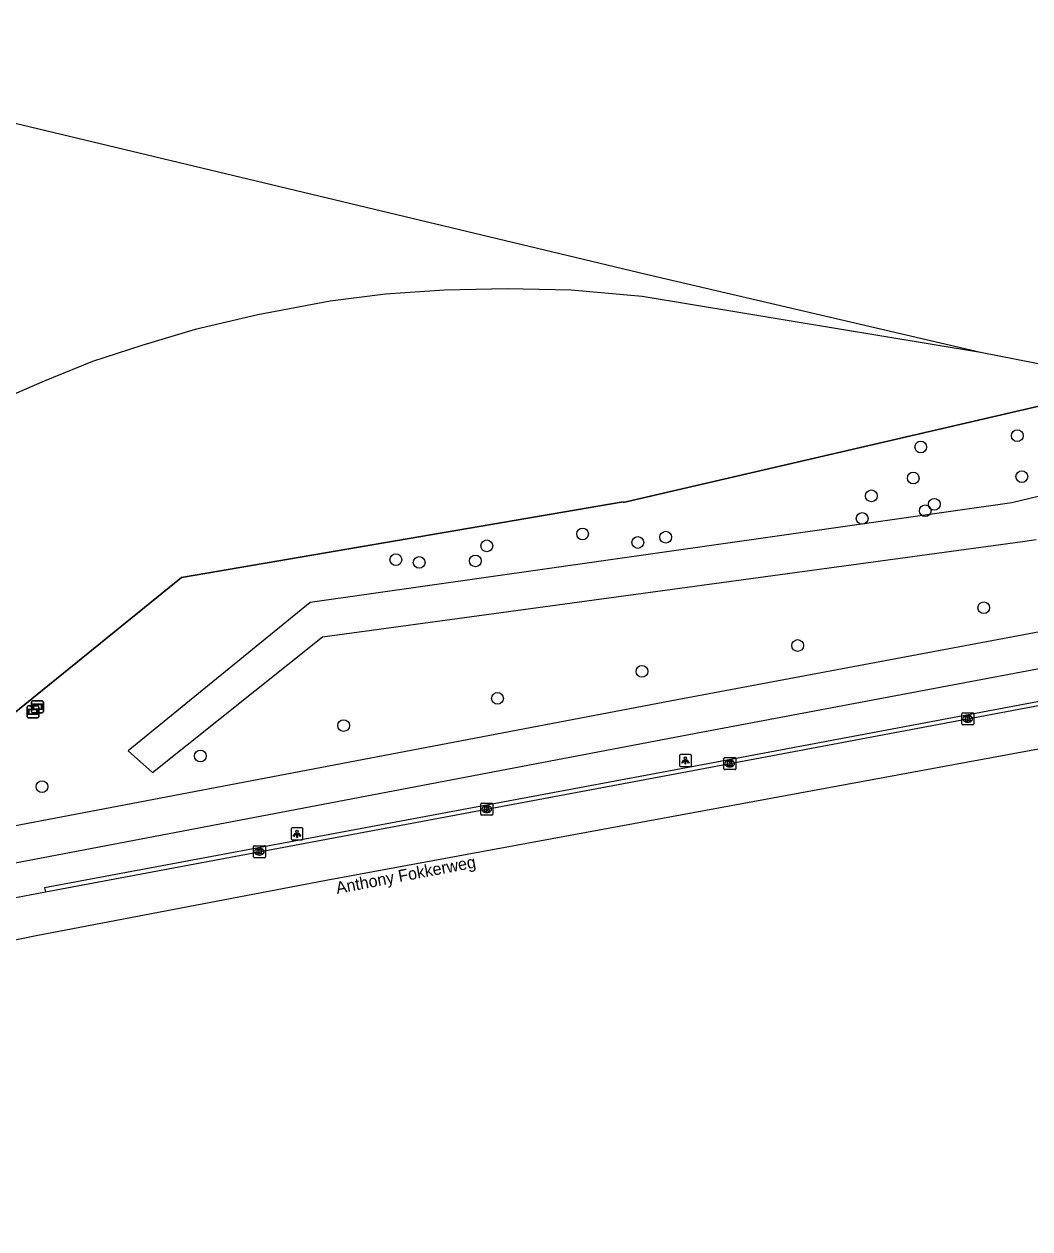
# Model space of a CAD drawing. Extents: x 156141 to 158132, y 385651 to 388399.
# Drawn here: x 157692.2 to 157776, y 386390.2 to 386490.4 of the extents above; entities that cross this region are included whole.
import ezdxf

# ---------------------------------------------------------------- set-up
doc = ezdxf.new("R2010")
doc.units = 0
for name, color, linetype in [('IMGEO_Boom', 7, 'Continuous'), ('IMGEO_Fietspad_gesloten', 7, 'Continuous'), ('IMGEO_Groenvoorziening', 7, 'Continuous'), ('IMGEO_Hek', 7, 'Continuous'), ('IMGEO_Kolk', 7, 'Continuous'), ('IMGEO_Lichtpunt', 7, 'Continuous'), ('IMGEO_Openbare_ruimte_label', 7, 'Continuous'), ('IMGEO_Rijbaan_regionaal_gesloten', 7, 'Continuous'), ('IMGEO_Spoor', 7, 'Continuous'), ('IMGEO_Verkeerseiland_open', 7, 'Continuous'), ('IMGEO_Verklikker', 7, 'Continuous')]:
    doc.layers.add(name, color=color, linetype=linetype)

msp = doc.modelspace()

# ---------------------------------------------------------------- linework, layer by layer
at = {"layer": 'IMGEO_Boom'}
for centre in [(157774.9, 386456.2), (157766.87, 386455.26), (157775.28, 386452.8), (157766.24, 386452.68), (157762.76, 386451.2), (157767.24, 386449.96), (157768, 386450.5), (157761.99, 386449.32), (157738.72, 386448.03), (157745.64, 386447.76), (157730.75, 386447.04), (157743.32, 386447.32), (157723.18, 386445.89), (157729.8, 386445.79), (157725.12, 386445.66), (157772.11, 386441.89), (157756.62, 386438.75), (157743.66, 386436.6), (157731.64, 386434.35), (157718.83, 386432.09), (157706.91, 386429.56), (157693.73, 386427.01)]:
    msp.add_circle(centre, 0.489, dxfattribs=at)
at = {"layer": 'IMGEO_Fietspad_gesloten'}
for points in [[(157813.76, 386446.82), (157746.6, 386434.23), (157685.54, 386422.6), (157681.31, 386421.73), (157676.8, 386420.73)], [(157677.29, 386417.7), (157686.09, 386419.66), (157747.11, 386431.27), (157814.29, 386443.91)]]:
    msp.add_lwpolyline(points, dxfattribs=at)
at = {"layer": 'IMGEO_Groenvoorziening'}
for points in [[(157679.82, 386423.74), (157705.33, 386444.41), (157742.09, 386450.7), (157742.11, 386450.66), (157779.34, 386459.26)], [(157799.75, 386456.7), (157774.45, 386450.61), (157716.05, 386442.34), (157700.91, 386430), (157702.93, 386428.18), (157717.07, 386439.48), (157775.34, 386447.41), (157776.46, 386447.56)]]:
    msp.add_lwpolyline(points, dxfattribs=at)
at = {"layer": 'IMGEO_Hek'}
for points in [[(157779.34, 386459.26), (157742.11, 386450.66), (157742.09, 386450.7), (157705.33, 386444.41)], [(157705.33, 386444.41), (157679.82, 386423.74)]]:
    msp.add_lwpolyline(points, dxfattribs=at)
at = {"layer": 'IMGEO_Kolk'}
for p, q in [((157770.36, 386433.16), (157771.21, 386433.16)), ((157770.28, 386432.23), (157770.28, 386433.08)), ((157771.21, 386432.15), (157770.36, 386432.15)), ((157770.77, 386432.93), (157770.79, 386432.93)), ((157770.79, 386432.38), (157770.77, 386432.38)), ((157771.28, 386433.08), (157771.28, 386432.23)), ((157750.47, 386428.5), (157750.47, 386429.35)), ((157750.55, 386429.43), (157751.4, 386429.43)), ((157750.96, 386429.21), (157750.99, 386429.21)), ((157751.47, 386429.35), (157751.47, 386428.5)), ((157751.4, 386428.43), (157750.55, 386428.43)), ((157750.98, 386428.65), (157750.96, 386428.65)), ((157730.25, 386424.71), (157730.25, 386425.56)), ((157730.32, 386425.64), (157731.17, 386425.64)), ((157730.73, 386425.42), (157730.76, 386425.42)), ((157731.25, 386425.56), (157731.25, 386424.71)), ((157731.17, 386424.64), (157730.32, 386424.64)), ((157730.76, 386424.86), (157730.73, 386424.86)), ((157711.32, 386421.17), (157711.32, 386422.03)), ((157711.39, 386422.1), (157712.25, 386422.1)), ((157711.83, 386421.32), (157711.8, 386421.32)), ((157711.81, 386421.88), (157711.83, 386421.88)), ((157712.32, 386422.03), (157712.32, 386421.17)), ((157712.25, 386421.1), (157711.39, 386421.1))]:
    msp.add_line(p, q, dxfattribs=at)
for points in [[(157770.36, 386433.16), (157771.21, 386433.16)], [(157770.28, 386432.23), (157770.28, 386433.08)], [(157771.21, 386432.15), (157770.36, 386432.15)], [(157770.6, 386432.85), (157770.73, 386432.85), (157770.73, 386432.7), (157770.85, 386432.85), (157771.02, 386432.85), (157770.87, 386432.7), (157771.03, 386432.45), (157770.87, 386432.45), (157770.79, 386432.62), (157770.73, 386432.55), (157770.73, 386432.45), (157770.6, 386432.45), (157770.6, 386432.85)], [(157771.28, 386433.08), (157771.28, 386432.23)], [(157750.47, 386428.5), (157750.47, 386429.35)], [(157750.55, 386429.43), (157751.4, 386429.43)], [(157750.79, 386429.13), (157750.92, 386429.13), (157750.92, 386428.98), (157751.05, 386429.13), (157751.21, 386429.13), (157751.06, 386428.98), (157751.22, 386428.73), (157751.06, 386428.73), (157750.98, 386428.89), (157750.92, 386428.83), (157750.92, 386428.73), (157750.79, 386428.73), (157750.79, 386429.13)], [(157751.47, 386429.35), (157751.47, 386428.5)], [(157751.4, 386428.43), (157750.55, 386428.43)], [(157730.25, 386424.71), (157730.25, 386425.56)], [(157730.32, 386425.64), (157731.17, 386425.64)], [(157730.57, 386425.34), (157730.69, 386425.34), (157730.69, 386425.19), (157730.82, 386425.34), (157730.98, 386425.34), (157730.84, 386425.19), (157730.99, 386424.94), (157730.84, 386424.94), (157730.75, 386425.1), (157730.69, 386425.03), (157730.69, 386424.94), (157730.57, 386424.94), (157730.57, 386425.34)], [(157731.25, 386425.56), (157731.25, 386424.71)], [(157731.17, 386424.64), (157730.32, 386424.64)], [(157711.32, 386421.17), (157711.32, 386422.03)], [(157711.39, 386422.1), (157712.25, 386422.1)], [(157711.64, 386421.8), (157711.76, 386421.8), (157711.76, 386421.65), (157711.89, 386421.8), (157712.06, 386421.8), (157711.91, 386421.65), (157712.06, 386421.4), (157711.91, 386421.4), (157711.83, 386421.56), (157711.76, 386421.5), (157711.76, 386421.4), (157711.64, 386421.4), (157711.64, 386421.8)], [(157712.32, 386422.03), (157712.32, 386421.17)], [(157712.25, 386421.1), (157711.39, 386421.1)]]:
    msp.add_lwpolyline(points, dxfattribs=at)
for centre, start, end in [((157770.36, 386433.08), 91.552, 178.448), ((157770.36, 386433.08), 91.552, 178.448), ((157771.21, 386433.08), 1.552, 88.448), ((157771.21, 386433.08), 1.552, 88.448), ((157770.36, 386432.23), 181.552, 268.448), ((157770.36, 386432.23), 181.552, 268.448), ((157771.21, 386432.23), 271.552, 358.448), ((157771.21, 386432.23), 271.552, 358.448), ((157750.55, 386429.35), 91.552, 178.448), ((157750.55, 386429.35), 91.552, 178.448), ((157751.4, 386429.35), 1.552, 88.448), ((157751.4, 386429.35), 1.552, 88.448), ((157750.55, 386428.5), 181.552, 268.448), ((157750.55, 386428.5), 181.552, 268.448), ((157751.4, 386428.5), 271.552, 358.448), ((157751.4, 386428.5), 271.552, 358.448), ((157730.32, 386425.56), 91.552, 178.448), ((157730.32, 386425.56), 91.552, 178.448), ((157731.17, 386425.56), 1.552, 88.448), ((157731.17, 386425.56), 1.552, 88.448), ((157730.32, 386424.71), 181.552, 268.448), ((157730.32, 386424.71), 181.552, 268.448), ((157731.17, 386424.71), 271.552, 358.448), ((157731.17, 386424.71), 271.552, 358.448), ((157711.4, 386422.02), 91.552, 178.448), ((157711.4, 386422.02), 91.552, 178.448), ((157711.4, 386421.17), 181.552, 268.448), ((157711.4, 386421.17), 181.552, 268.448), ((157712.24, 386422.02), 1.552, 88.448), ((157712.24, 386422.02), 1.552, 88.448), ((157712.24, 386421.17), 271.552, 358.448), ((157712.24, 386421.17), 271.552, 358.448)]:
    msp.add_arc(centre, 0.0765, start, end, dxfattribs=at)
for centre, major_axis, ratio, start_param, end_param in [((157770.77, 386432.65), (-0.387, 0.002), 0.722429, 4.712389, 7.853982), ((157770.79, 386432.65), (-0.39, 0.002), 0.717154, 1.570796, 4.712389), ((157750.96, 386428.93), (-0.387, 0.002), 0.722429, 4.712389, 7.853982), ((157750.98, 386428.93), (-0.39, 0.002), 0.717154, 1.570796, 4.712389), ((157730.73, 386425.14), (-0.387, 0.002), 0.722429, 4.712389, 7.853982), ((157730.76, 386425.14), (-0.39, 0.002), 0.717154, 1.570796, 4.712389), ((157711.81, 386421.6), (-0.387, 0.002), 0.722429, 4.712389, 7.853982), ((157711.83, 386421.6), (-0.39, 0.002), 0.717154, 1.570796, 4.712389)]:
    msp.add_ellipse(centre, major_axis=major_axis, ratio=ratio, start_param=start_param, end_param=end_param, dxfattribs=at)
at = {"layer": 'IMGEO_Lichtpunt'}
for p, q in [((157746.78, 386429.58), (157746.78, 386428.77)), ((157746.78, 386429.58), (157746.78, 386428.77)), ((157747.68, 386429.68), (157746.87, 386429.68)), ((157747.68, 386429.68), (157746.87, 386429.68)), ((157747.78, 386428.77), (157747.78, 386429.58)), ((157747.78, 386428.77), (157747.78, 386429.58)), ((157746.87, 386428.68), (157747.68, 386428.68)), ((157746.87, 386428.68), (157747.68, 386428.68)), ((157714.46, 386423.49), (157714.46, 386422.68)), ((157714.46, 386423.49), (157714.46, 386422.68)), ((157715.36, 386423.59), (157714.55, 386423.59)), ((157715.36, 386423.59), (157714.55, 386423.59)), ((157715.45, 386422.68), (157715.45, 386423.49)), ((157715.45, 386422.68), (157715.45, 386423.49)), ((157714.55, 386422.59), (157715.36, 386422.59)), ((157714.55, 386422.59), (157715.36, 386422.59))]:
    msp.add_line(p, q, dxfattribs=at)
for points in [[(157747.15, 386429.24), (157747.19, 386429.22), (157747.01, 386428.95), (157746.97, 386428.98), (157747.15, 386429.24)], [(157747.26, 386429.2), (157747.3, 386429.2), (157747.3, 386428.87), (157747.26, 386428.87), (157747.26, 386429.2)], [(157747.37, 386429.22), (157747.4, 386429.24), (157747.59, 386428.98), (157747.55, 386428.95), (157747.37, 386429.22)], [(157714.83, 386423.15), (157714.87, 386423.13), (157714.68, 386422.86), (157714.64, 386422.89), (157714.83, 386423.15)], [(157715.04, 386423.13), (157715.08, 386423.15), (157715.27, 386422.89), (157715.23, 386422.86), (157715.04, 386423.13)], [(157714.93, 386423.11), (157714.98, 386423.11), (157714.98, 386422.78), (157714.93, 386422.78), (157714.93, 386423.11)]]:
    msp.add_lwpolyline(points, dxfattribs=at)
for centre in [(157747.28, 386429.38), (157714.96, 386423.29)]:
    msp.add_circle(centre, 0.0994, dxfattribs=at)
for centre, start, end in [((157746.87, 386429.58), 90, 180), ((157746.87, 386429.58), 90, 180), ((157747.68, 386429.58), 0, 90), ((157747.68, 386429.58), 0, 90), ((157746.87, 386428.77), 180, 270), ((157746.87, 386428.77), 180, 270), ((157747.68, 386428.77), 270, 0), ((157747.68, 386428.77), 270, 360), ((157714.55, 386423.49), 90, 180), ((157714.55, 386423.49), 90, 180), ((157715.36, 386423.49), 0, 90), ((157715.36, 386423.49), 0, 90), ((157714.55, 386422.68), 180, 270), ((157714.55, 386422.68), 180, 270), ((157715.36, 386422.68), 270, 0), ((157715.36, 386422.68), 270, 360)]:
    msp.add_arc(centre, 0.0946, start, end, dxfattribs=at)
at = {"layer": 'IMGEO_Rijbaan_regionaal_gesloten'}
for points in [[(157694.01, 386418.27), (157747.45, 386428.26), (157813.23, 386440.64), (157839.89, 386446.74), (157865.93, 386454.43), (157891.9, 386464.42), (157918.1, 386476.5)], [(157914.39, 386470.43), (157903.17, 386465.1), (157889.67, 386459.09), (157888.96, 386458.78), (157875.33, 386453.59), (157866.1, 386450.54), (157854.31, 386446.77), (157841.03, 386443.01), (157830.52, 386440.45), (157817.02, 386437.47), (157780.59, 386430.86), (157717.39, 386419.2), (157693.24, 386414.59), (157682.38, 386412.38)], [(157684.08, 386416.37), (157694.01, 386418.27)]]:
    msp.add_lwpolyline(points, dxfattribs=at)
at = {"layer": 'IMGEO_Spoor'}
for points in [[(157910.78, 386490.44), (157897.77, 386484.55), (157884.9, 386479.08), (157872.28, 386473.93), (157865.09, 386471.17), (157853.79, 386467.14), (157848.15, 386465.39), (157843.02, 386463.98), (157837.26, 386462.56), (157831.93, 386461.38), (157823.79, 386459.92), (157820.12, 386459.44), (157814, 386459.06), (157808.96, 386459.02), (157801.86, 386459.27), (157794.87, 386459.67), (157787.6, 386460.44), (157779.32, 386461.65), (157771.85, 386463.12)], [(157744.01, 386469.62), (157691.49, 386482.17), (157686.23, 386483.23), (157680.66, 386484.02), (157673.45, 386484.68), (157667.87, 386484.92), (157662.02, 386485.01), (157655.78, 386484.87), (157649.9, 386484.5), (157646.62, 386484.19), (157641.95, 386483.58), (157638.57, 386482.96), (157636.11, 386482.31)], [(157771.85, 386463.12), (157744.01, 386469.62)], [(157743.69, 386467.77), (157737.76, 386468.32), (157732.45, 386468.42), (157727.23, 386468.32), (157722.32, 386467.99), (157717.72, 386467.39), (157711.69, 386466.27), (157706.48, 386465.04), (157702.03, 386463.71), (157697.93, 386462.37), (157693.91, 386460.75), (157689.92, 386459.03), (157685.32, 386456.68), (157651.06, 386438.03), (157642.92, 386433.88), (157636.31, 386430.68), (157629.32, 386427.49), (157623.89, 386425.12), (157612.03, 386420.23), (157594.4, 386413.28), (157582.3, 386408.25), (157573.12, 386404.15), (157564.55, 386400.1), (157544.39, 386390.22)], [(157771.85, 386463.12), (157743.69, 386467.77)]]:
    msp.add_lwpolyline(points, dxfattribs=at)
at = {"layer": 'IMGEO_Verkeerseiland_open'}
msp.add_lwpolyline([(157813.17, 386440.93), (157747.36, 386428.58), (157693.94, 386418.58), (157694.01, 386418.27)], dxfattribs=at)
at = {"layer": 'IMGEO_Verklikker'}
for p, q in [((157692.95, 386434.15), (157693.74, 386434.15)), ((157693.74, 386434.15), (157692.95, 386434.15)), ((157692.48, 386432.83), (157692.48, 386433.63)), ((157692.48, 386433.63), (157692.48, 386432.83)), ((157692.58, 386433.73), (157693.36, 386433.73)), ((157693.36, 386433.73), (157692.58, 386433.73)), ((157692.85, 386433.25), (157692.85, 386434.05)), ((157692.85, 386434.05), (157692.85, 386433.25)), ((157693.74, 386433.15), (157692.95, 386433.15)), ((157692.95, 386433.15), (157693.74, 386433.15)), ((157693.46, 386433.63), (157693.46, 386432.83)), ((157693.46, 386432.83), (157693.46, 386433.63)), ((157693.84, 386434.05), (157693.84, 386433.25)), ((157693.84, 386433.25), (157693.84, 386434.05)), ((157693.36, 386432.73), (157692.58, 386432.73)), ((157692.58, 386432.73), (157693.36, 386432.73))]:
    msp.add_line(p, q, dxfattribs=at)
for points in [[(157692.58, 386433.46), (157693.36, 386433.46), (157693.36, 386433), (157692.58, 386433), (157692.58, 386433.46)], [(157692.64, 386433.4), (157692.64, 386433.06), (157693.3, 386433.06), (157693.3, 386433.4), (157692.64, 386433.4)], [(157692.95, 386433.89), (157693.74, 386433.89), (157693.74, 386433.42), (157692.95, 386433.42), (157692.95, 386433.89)], [(157693.02, 386433.82), (157693.02, 386433.49), (157693.68, 386433.49), (157693.68, 386433.82), (157693.02, 386433.82)]]:
    msp.add_lwpolyline(points, dxfattribs=at)
for centre, start, end in [((157692.95, 386434.05), 90, 180), ((157692.95, 386434.05), 90, 180), ((157693.74, 386434.05), 0, 90), ((157693.74, 386434.05), 360, 90), ((157692.58, 386433.63), 90, 180), ((157692.58, 386433.63), 90, 180), ((157692.95, 386433.25), 180, 270), ((157692.95, 386433.25), 180, 270), ((157693.36, 386433.63), 0, 90), ((157693.36, 386433.63), 360, 90), ((157693.74, 386433.25), 270, 0), ((157693.74, 386433.25), 270, 0), ((157692.58, 386432.83), 180, 270), ((157692.58, 386432.83), 180, 270), ((157693.36, 386432.83), 270, 0), ((157693.36, 386432.83), 270, 0)]:
    msp.add_arc(centre, 0.1, start, end, dxfattribs=at)

# ---------------------------------------------------------------- texts
at = {"layer": 'IMGEO_Openbare_ruimte_label'}
msp.add_text('Anthony Fokkerweg', height=1, rotation=10.7816, dxfattribs=at).set_placement((157718.29, 386418.08))

doc.saveas('drawing.dxf')
